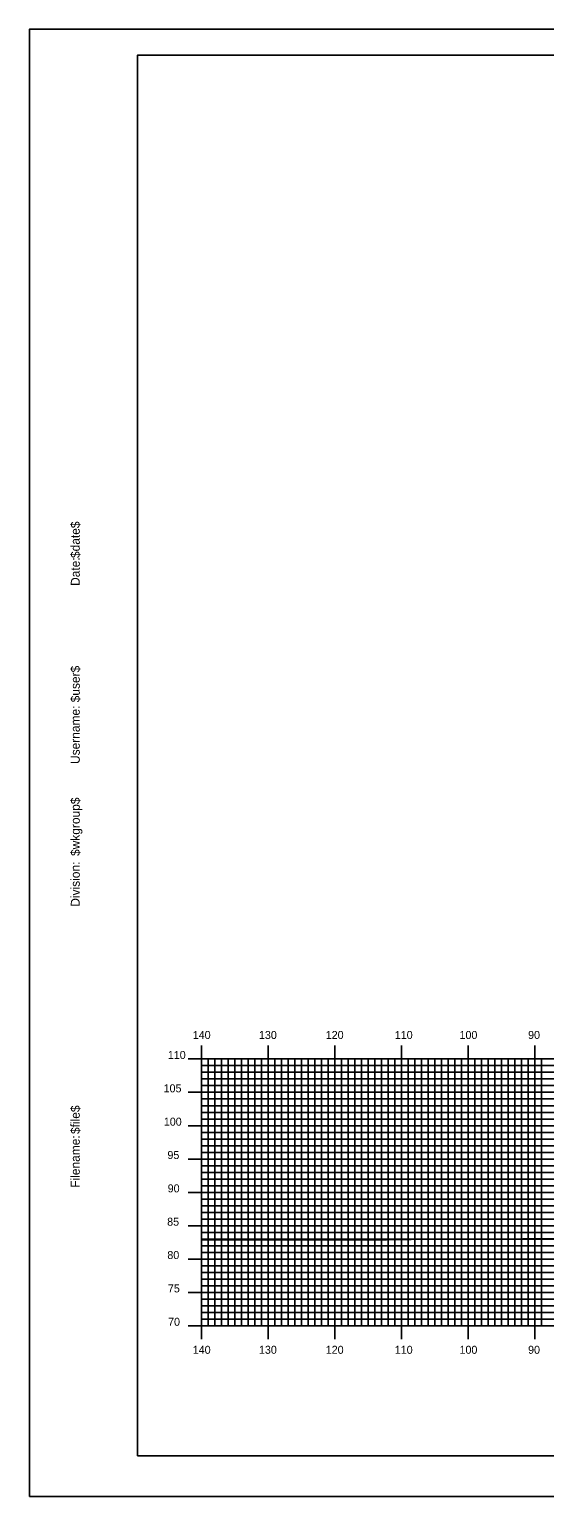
# Model space of a CAD drawing. Extents: x 1758647 to 1758990, y 442323 to 442543.
# Drawn here: x 1758646.6 to 1758723.9, y 442323.3 to 442543.3 of the extents above; entities that cross this region are included whole.
import ezdxf

# ---------------------------------------------------------------- set-up
doc = ezdxf.new("R2010")
doc.units = 0
for name, color, linetype in [('BORDER', 7, 'Continuous'), ('H_V ANNOTATION', 7, 'Continuous'), ('MAJOR', 7, 'Continuous'), ('MINOR', 7, 'Continuous'), ('PLOT BOUNDARY', 7, 'Continuous'), ('S_Roadway_Centerline', 7, 'Continuous')]:
    doc.layers.add(name, color=color, linetype=linetype)

msp = doc.modelspace()

# ---------------------------------------------------------------- linework, layer by layer
at = {"layer": 'BORDER'}
msp.add_lwpolyline([(1758662.82, 442329.39), (1758982.82, 442329.39), (1758982.82, 442539.39), (1758662.82, 442539.39)], close=True, dxfattribs=at)
at = {"layer": 'MAJOR'}
for p, q in [((1758672.42, 442390.89), (1758672.42, 442388.89)), ((1758682.42, 442390.89), (1758682.42, 442388.89)), ((1758692.42, 442390.89), (1758692.42, 442388.89)), ((1758702.42, 442390.89), (1758702.42, 442388.89)), ((1758712.42, 442390.89), (1758712.42, 442388.89)), ((1758722.42, 442390.89), (1758722.42, 442388.89)), ((1758670.42, 442388.89), (1758672.42, 442388.89)), ((1758672.42, 442388.89), (1758952.42, 442388.89)), ((1758672.42, 442348.89), (1758672.42, 442388.89)), ((1758672.42, 442348.89), (1758672.42, 442388.89)), ((1758672.42, 442388.89), (1758952.42, 442388.89)), ((1758682.42, 442348.89), (1758682.42, 442388.89)), ((1758692.42, 442348.89), (1758692.42, 442388.89)), ((1758702.42, 442348.89), (1758702.42, 442388.89)), ((1758712.42, 442348.89), (1758712.42, 442388.89)), ((1758722.42, 442348.89), (1758722.42, 442388.89)), ((1758670.42, 442383.89), (1758672.42, 442383.89)), ((1758672.42, 442383.89), (1758952.42, 442383.89)), ((1758670.42, 442378.89), (1758672.42, 442378.89)), ((1758672.42, 442378.89), (1758952.42, 442378.89)), ((1758670.42, 442373.89), (1758672.42, 442373.89)), ((1758672.42, 442373.89), (1758952.42, 442373.89)), ((1758670.42, 442368.89), (1758672.42, 442368.89)), ((1758672.42, 442368.89), (1758952.42, 442368.89)), ((1758670.42, 442363.89), (1758672.42, 442363.89)), ((1758672.42, 442363.89), (1758952.42, 442363.89)), ((1758670.42, 442358.89), (1758672.42, 442358.89)), ((1758672.42, 442358.89), (1758952.42, 442358.89)), ((1758670.42, 442353.89), (1758672.42, 442353.89)), ((1758672.42, 442353.89), (1758952.42, 442353.89)), ((1758670.42, 442348.89), (1758672.42, 442348.89)), ((1758672.42, 442348.89), (1758952.42, 442348.89)), ((1758672.42, 442348.89), (1758952.42, 442348.89)), ((1758672.42, 442346.88), (1758672.42, 442348.89)), ((1758682.42, 442346.88), (1758682.42, 442348.89)), ((1758692.42, 442346.88), (1758692.42, 442348.89)), ((1758702.42, 442346.88), (1758702.42, 442348.89)), ((1758712.42, 442346.88), (1758712.42, 442348.89)), ((1758722.42, 442346.88), (1758722.42, 442348.89))]:
    msp.add_line(p, q, dxfattribs=at)
at = {"layer": 'MINOR'}
for p, q in [((1758672.42, 442387.89), (1758952.42, 442387.89)), ((1758672.42, 442387.89), (1758674.43, 442387.89)), ((1758673.42, 442348.89), (1758673.42, 442388.89)), ((1758674.42, 442348.89), (1758674.42, 442388.89)), ((1758675.42, 442348.89), (1758675.42, 442388.89)), ((1758676.42, 442348.89), (1758676.42, 442388.89)), ((1758677.42, 442348.89), (1758677.42, 442388.89)), ((1758678.42, 442348.89), (1758678.42, 442388.89)), ((1758679.42, 442348.89), (1758679.42, 442388.89)), ((1758680.42, 442348.89), (1758680.42, 442388.89)), ((1758681.42, 442348.89), (1758681.42, 442388.89)), ((1758683.42, 442348.89), (1758683.42, 442388.89)), ((1758684.42, 442348.89), (1758684.42, 442388.89)), ((1758685.42, 442348.89), (1758685.42, 442388.89)), ((1758686.42, 442348.89), (1758686.42, 442388.89)), ((1758687.42, 442348.89), (1758687.42, 442388.89)), ((1758688.42, 442348.89), (1758688.42, 442388.89)), ((1758689.42, 442348.89), (1758689.42, 442388.89)), ((1758690.42, 442348.89), (1758690.42, 442388.89)), ((1758691.42, 442348.89), (1758691.42, 442388.89)), ((1758693.42, 442348.89), (1758693.42, 442388.89)), ((1758694.42, 442348.89), (1758694.42, 442388.89)), ((1758695.42, 442348.89), (1758695.42, 442388.89)), ((1758696.42, 442348.89), (1758696.42, 442388.89)), ((1758697.42, 442348.89), (1758697.42, 442388.89)), ((1758698.42, 442348.89), (1758698.42, 442388.89)), ((1758699.42, 442348.89), (1758699.42, 442388.89)), ((1758700.42, 442348.89), (1758700.42, 442388.89)), ((1758701.42, 442348.89), (1758701.42, 442388.89)), ((1758703.42, 442348.89), (1758703.42, 442388.89)), ((1758704.42, 442348.89), (1758704.42, 442388.89)), ((1758705.42, 442348.89), (1758705.42, 442388.89)), ((1758706.42, 442348.89), (1758706.42, 442388.89)), ((1758707.42, 442348.89), (1758707.42, 442388.89)), ((1758708.42, 442348.89), (1758708.42, 442388.89)), ((1758709.42, 442348.89), (1758709.42, 442388.89)), ((1758710.42, 442348.89), (1758710.42, 442388.89)), ((1758711.42, 442348.89), (1758711.42, 442388.89)), ((1758713.42, 442348.89), (1758713.42, 442388.89)), ((1758714.42, 442348.89), (1758714.42, 442388.89)), ((1758715.42, 442348.89), (1758715.42, 442388.89)), ((1758716.42, 442348.89), (1758716.42, 442388.89)), ((1758717.42, 442348.89), (1758717.42, 442388.89)), ((1758718.42, 442348.89), (1758718.42, 442388.89)), ((1758719.42, 442348.89), (1758719.42, 442388.89)), ((1758720.42, 442348.89), (1758720.42, 442388.89)), ((1758721.42, 442348.89), (1758721.42, 442388.89)), ((1758723.42, 442348.89), (1758723.42, 442388.89)), ((1758672.42, 442386.89), (1758952.42, 442386.89)), ((1758672.42, 442386.89), (1758674.43, 442386.89)), ((1758672.42, 442385.89), (1758952.42, 442385.89)), ((1758672.42, 442385.89), (1758674.43, 442385.89)), ((1758672.42, 442384.89), (1758952.42, 442384.89)), ((1758672.42, 442384.89), (1758674.43, 442384.89)), ((1758672.42, 442382.89), (1758952.42, 442382.89)), ((1758672.42, 442382.89), (1758674.43, 442382.89)), ((1758672.42, 442381.89), (1758952.42, 442381.89)), ((1758672.42, 442381.89), (1758674.43, 442381.89)), ((1758672.42, 442380.89), (1758952.42, 442380.89)), ((1758672.42, 442380.89), (1758674.43, 442380.89)), ((1758672.42, 442379.89), (1758952.42, 442379.89)), ((1758672.42, 442379.89), (1758674.43, 442379.89)), ((1758672.42, 442377.89), (1758952.42, 442377.89)), ((1758672.42, 442377.89), (1758674.43, 442377.89)), ((1758672.42, 442376.89), (1758952.42, 442376.89)), ((1758672.42, 442376.89), (1758674.43, 442376.89)), ((1758672.42, 442375.89), (1758952.42, 442375.89)), ((1758672.42, 442375.89), (1758674.43, 442375.89)), ((1758672.42, 442374.89), (1758952.42, 442374.89)), ((1758672.42, 442374.89), (1758674.43, 442374.89)), ((1758672.42, 442372.89), (1758952.42, 442372.89)), ((1758672.42, 442372.89), (1758674.43, 442372.89)), ((1758672.42, 442371.89), (1758952.42, 442371.89)), ((1758672.42, 442371.89), (1758674.43, 442371.89)), ((1758672.42, 442370.89), (1758952.42, 442370.89)), ((1758672.42, 442370.89), (1758674.43, 442370.89)), ((1758672.42, 442369.89), (1758952.42, 442369.89)), ((1758672.42, 442369.89), (1758674.43, 442369.89)), ((1758672.42, 442367.89), (1758952.42, 442367.89)), ((1758672.42, 442367.89), (1758674.43, 442367.89)), ((1758672.42, 442366.89), (1758952.42, 442366.89)), ((1758672.42, 442366.89), (1758674.43, 442366.89)), ((1758672.42, 442365.89), (1758952.42, 442365.89)), ((1758672.42, 442365.89), (1758674.43, 442365.89)), ((1758672.42, 442364.89), (1758952.42, 442364.89)), ((1758672.42, 442364.89), (1758674.43, 442364.89)), ((1758672.42, 442362.89), (1758952.42, 442362.89)), ((1758672.42, 442362.89), (1758674.43, 442362.89)), ((1758672.42, 442361.89), (1758952.42, 442361.89)), ((1758672.42, 442361.89), (1758674.43, 442361.89)), ((1758672.42, 442360.89), (1758952.42, 442360.89)), ((1758672.42, 442360.89), (1758674.43, 442360.89)), ((1758672.42, 442359.89), (1758952.42, 442359.89)), ((1758672.42, 442359.89), (1758674.43, 442359.89)), ((1758672.42, 442357.89), (1758952.42, 442357.89)), ((1758672.42, 442357.89), (1758674.43, 442357.89)), ((1758672.42, 442356.89), (1758952.42, 442356.89)), ((1758672.42, 442356.89), (1758674.43, 442356.89)), ((1758672.42, 442355.89), (1758952.42, 442355.89)), ((1758672.42, 442355.89), (1758674.43, 442355.89)), ((1758672.42, 442354.89), (1758952.42, 442354.89)), ((1758672.42, 442354.89), (1758674.43, 442354.89)), ((1758672.42, 442352.89), (1758952.42, 442352.89)), ((1758672.42, 442352.89), (1758674.43, 442352.89)), ((1758672.42, 442351.89), (1758952.42, 442351.89)), ((1758672.42, 442351.89), (1758674.43, 442351.89)), ((1758672.42, 442350.89), (1758952.42, 442350.89)), ((1758672.42, 442350.89), (1758674.43, 442350.89)), ((1758672.42, 442349.89), (1758952.42, 442349.89)), ((1758672.42, 442349.89), (1758674.43, 442349.89))]:
    msp.add_line(p, q, dxfattribs=at)
at = {"layer": 'PLOT BOUNDARY'}
msp.add_lwpolyline([(1758646.64, 442323.27), (1758986.64, 442323.27), (1758986.64, 442543.27), (1758646.64, 442543.27)], close=True, dxfattribs=at)
at = {"layer": 'S_Roadway_Centerline'}
msp.add_lwpolyline([(1758672.42, 442361.77), (1758672.7, 442361.77), (1758690.63, 442361.76), (1758696.48, 442361.73), (1758707.57, 442361.87), (1758718.97, 442361.89), (1758720.62, 442361.93), (1758728.03, 442361.91)], dxfattribs=at)

# ---------------------------------------------------------------- texts
at = {"layer": 'BORDER'}
for s, p in [('$date$', (1758654.19, 442464)), ('Date:', (1758654.19, 442459.82)), ('$user$', (1758654.19, 442442.37)), ('Username:', (1758654.19, 442433.12)), ('$wkgroup$', (1758654.19, 442419.33)), ('Division:', (1758654.19, 442411.72)), ('$file$', (1758654.19, 442377.64)), ('Filename:', (1758654.19, 442369.58))]:
    msp.add_text(s, height=1.339, rotation=90, dxfattribs=at).set_placement(p)
at = {"layer": 'H_V ANNOTATION'}
for s, p in [('140', (1758671.13, 442391.89)), ('130', (1758681.05, 442391.89)), ('120', (1758691.06, 442391.89)), ('110', (1758701.41, 442391.89)), ('100', (1758711.11, 442391.89)), ('90', (1758721.39, 442391.89)), ('110', (1758667.39, 442388.89)), ('105', (1758666.76, 442383.89)), ('100', (1758666.79, 442378.89)), ('95', (1758667.33, 442373.89)), ('90', (1758667.37, 442368.89)), ('85', (1758667.29, 442363.89)), ('80', (1758667.32, 442358.89)), ('75', (1758667.4, 442353.89)), ('70', (1758667.43, 442348.89)), ('140', (1758671.13, 442344.69)), ('130', (1758681.05, 442344.69)), ('120', (1758691.06, 442344.69)), ('110', (1758701.41, 442344.69)), ('100', (1758711.11, 442344.69)), ('90', (1758721.39, 442344.69))]:
    msp.add_text(s, height=1.2, dxfattribs=at).set_placement(p)

doc.saveas('drawing.dxf')
